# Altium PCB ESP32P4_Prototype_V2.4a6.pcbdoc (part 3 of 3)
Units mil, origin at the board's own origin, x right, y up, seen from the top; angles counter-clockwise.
Board outline 8474.8 x 7265.9 mil, 6 copper layers (Top Layer, GND, VCC, VCC1, GND1, Bottom Layer), stack 62.3 mil thick; 189 components, 155 nets, 775 pads, 406 vias.
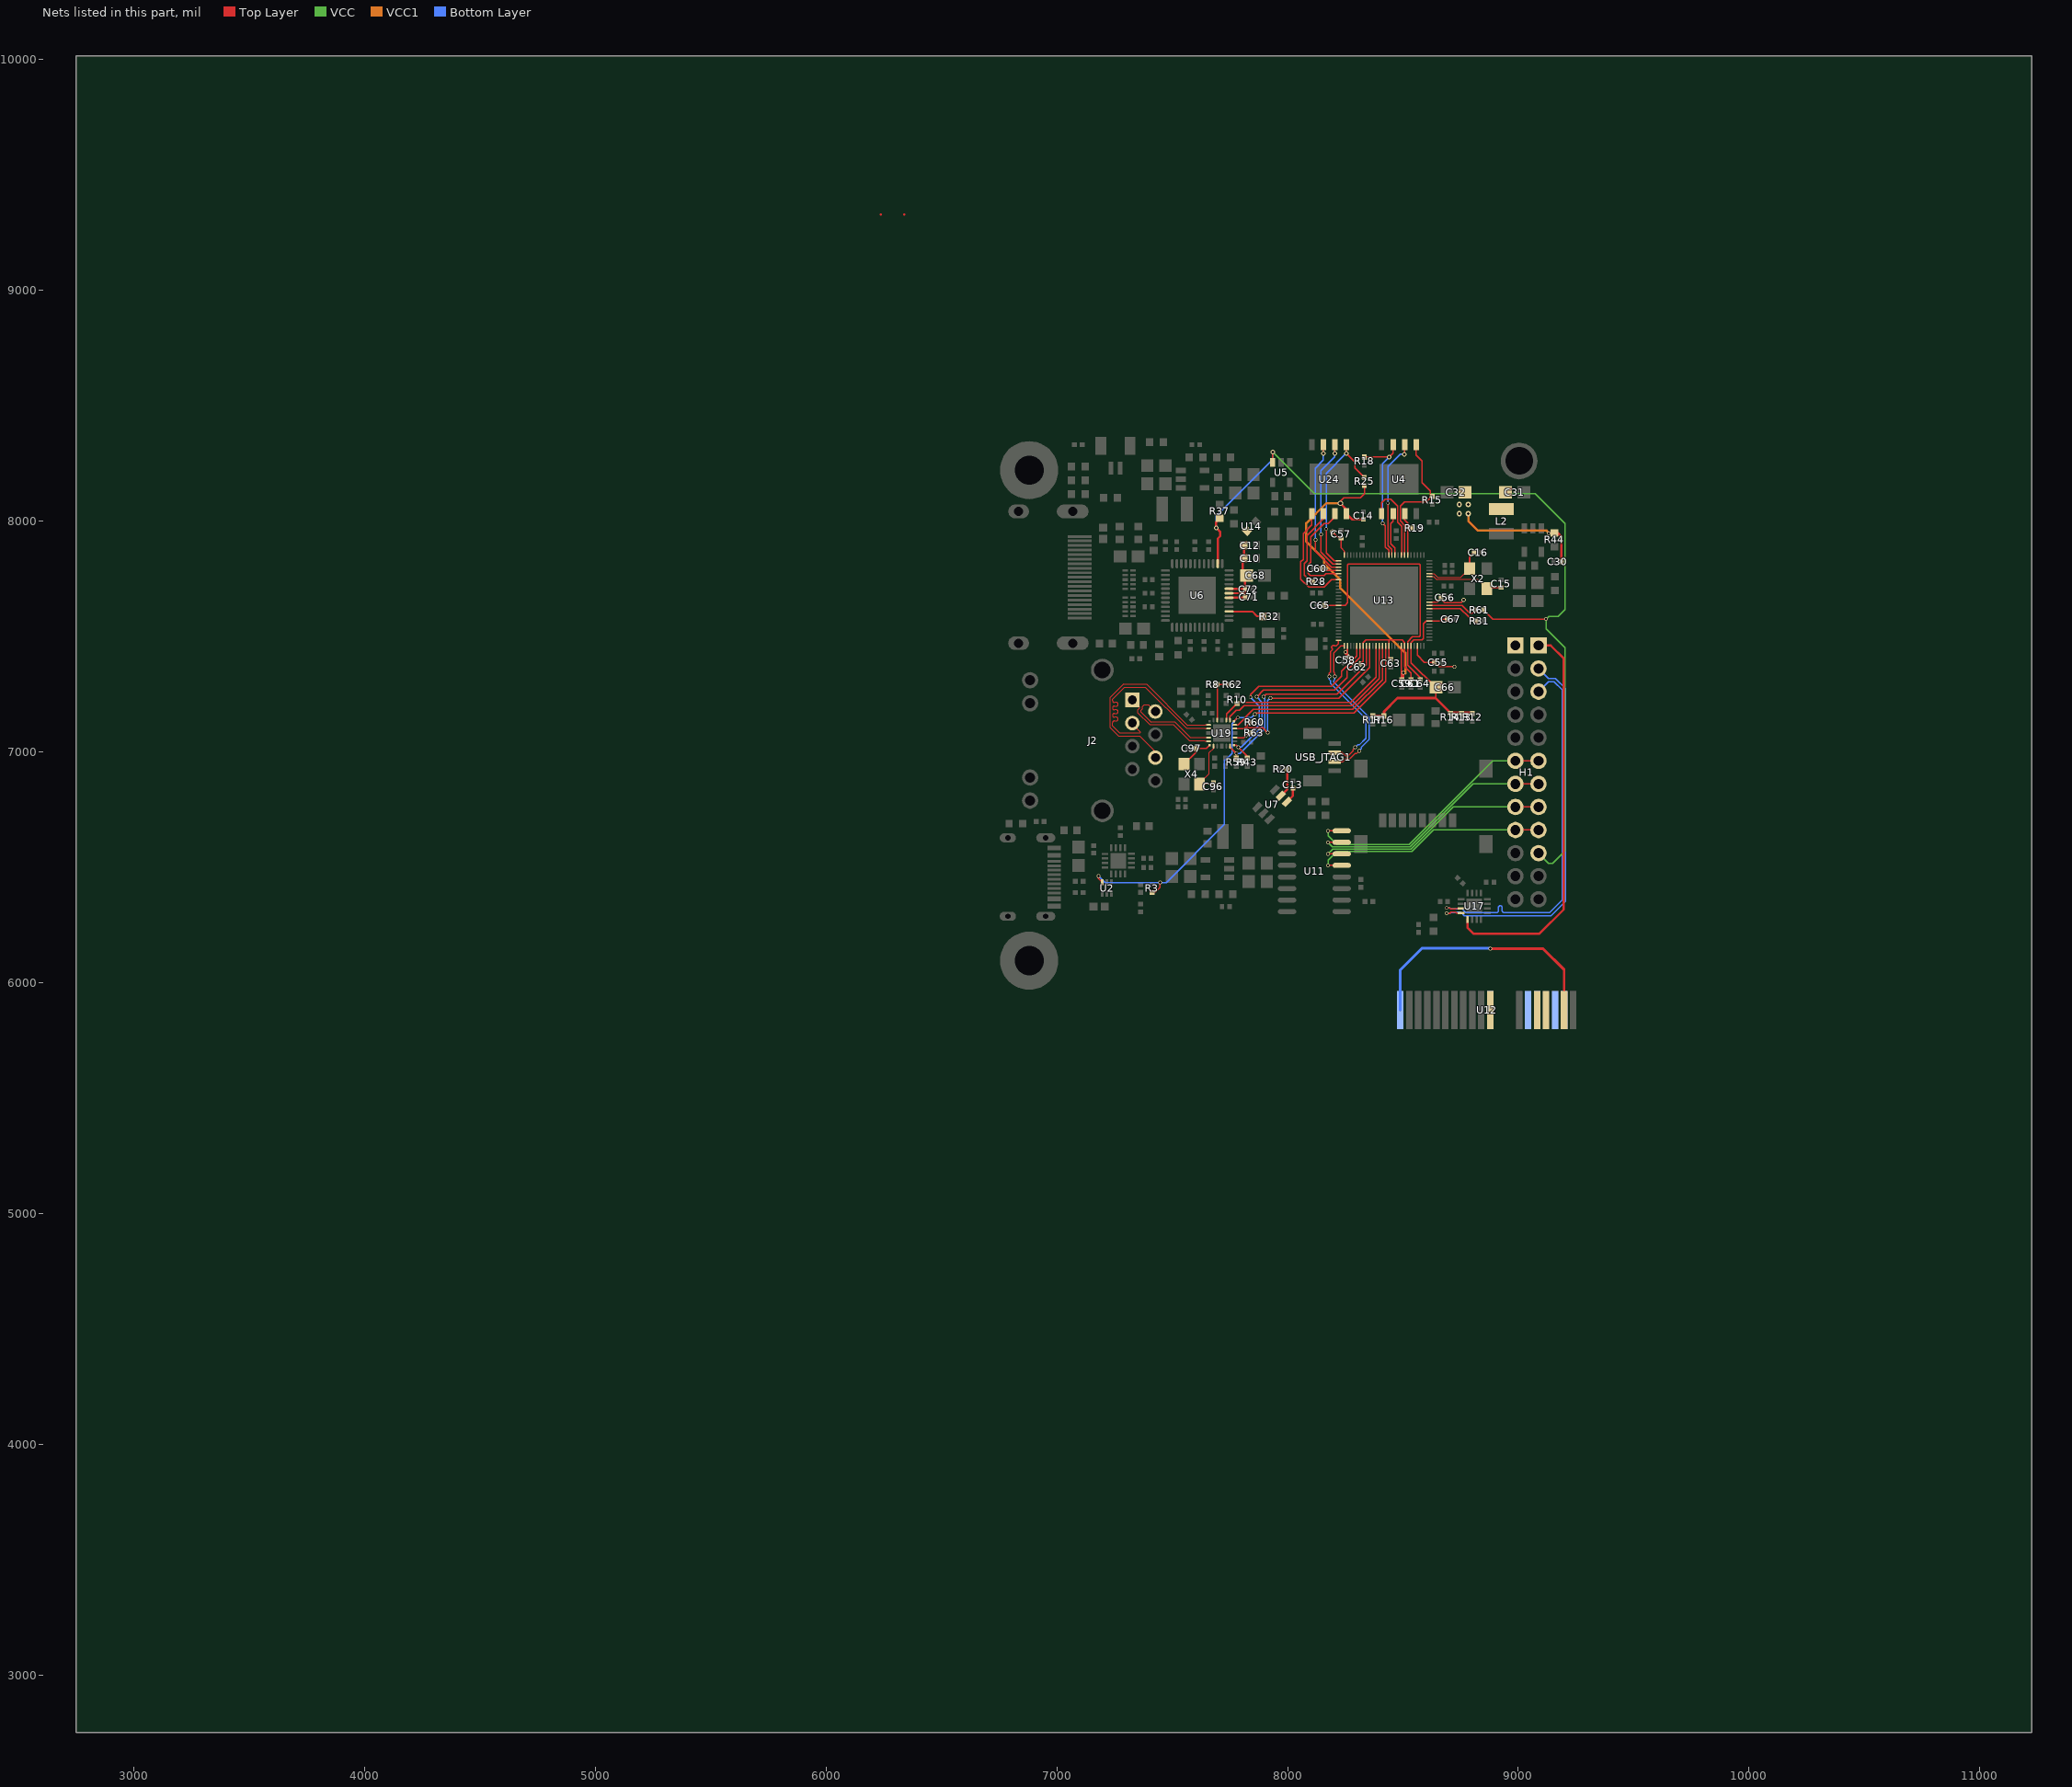
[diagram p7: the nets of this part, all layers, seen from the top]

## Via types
v1: diameter 15.7, hole 11.8, Top Layer to Bottom Layer, 168 vias
v2: diameter 23.6, hole 11.8, Top Layer to Bottom Layer, 139 vias
v3: diameter 19.7, hole 11.8, Top Layer to Bottom Layer, 91 vias
v4: diameter 23.6, hole 15.7, Top Layer to Bottom Layer, 8 vias

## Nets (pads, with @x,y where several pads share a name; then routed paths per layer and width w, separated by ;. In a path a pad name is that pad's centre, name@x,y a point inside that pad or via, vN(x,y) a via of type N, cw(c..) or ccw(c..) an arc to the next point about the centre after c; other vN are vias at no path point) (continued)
MS_SDA: H1.5 R37.1 R61.1 U5.3 U6.14 | length 4034.6
  Top Layer w5.9: R61.1@8849.6,7615 8889.1,7575.6 v1(9120.2,7575.6)
  Top Layer w6.1: U5.3@7935.2,8260.6 v3(7935.2,8299.9)
  Top Layer w10: U6.14@7697,7815.7 7697,7924 7708.8,7935.8 7708.8,7953 v3(7690.2,7971.6) 7690.2,7996.3 R37.1@7706.8,8012.9
  VCC w5.9: v3(7935.2,8299.9) 8116.5,8118.6 9073.2,8118.6 9202.9,7988.9 9202.9,7617.7 9172.6,7587.4 9132,7587.4 v1(9120.2,7575.6) 9120.2,7534.2 9202.9,7451.5 9202.9,6571.6 9148.7,6517.5 9131.5,6517.5 H1.5@9087.6,6561.4
  Bottom Layer w6.1: v3(7690.2,7971.6) 7690.2,8021.3 7935.2,8266.3 v3(7935.2,8299.9)
NET6: R20.1 U7.5 | length 130
  Top Layer w10: U7.5@7970.8,6810 7998.2,6837.4 7998.2,6919.4 R20.1@7991.6,6925.9
NET7: C13.2 U7.4 | length 69.4
  Top Layer w10: U7.4@7997.2,6783.5 8023.7,6810 C13.2@8023.7,6841.9
P4_FLASH_CK: R28.1 U24.6 | length 354.2
  Top Layer w5.9: R28.1@8108,7738.7 8100.8,7738.7 8073,7766.5 8073,7817.1 8083.8,7827.9 8083.8,7938.7 8154.9,8009.8 U24.6@8154.9,8040.3
P4_FLASH_CS: R25.2 U13.27 U24.1 | length 717.3
  Top Layer w5.9: v1(8168.1,7965.7) 8168.1,7862.3 8202,7828.4 U13.27@8220.9,7828.4 ; U24.1@8254.9,8339.5 v3(8254.9,8294.3) 8292,8257.2 8292,8230.1 R25.2@8332.8,8189.2
  Bottom Layer w5.9: v1(8168.1,7965.7) 8168.1,8207.5 v3(8254.9,8294.3)
P4_FLASH_D: U13.33 U24.5 | length 502.6
  Top Layer w5.9: U24.5@8104.9,8040.3 8104.9,7983.4 8067.8,7946.3 8067.8,7834.1 8057.2,7823.6 8057.2,7749.1 8092.7,7713.7 8157.6,7713.7 8189.7,7745.8 U13.33@8220.9,7745.8
P4_FLASH_HOLD: U13.31 U24.7 | length 457
  Top Layer w5.9: U24.7@8204.9,8032.3 8204.9,8018.5 8175.3,7988.9 8157.6,7988.9 8099.8,7931.1 8099.8,7821.6 8088.7,7810.5 8088.7,7774.4 8099.4,7763.7 8157.6,7763.7 8167.2,7773.3 U13.31@8220.9,7773.3
P4_FLASH_Q: U13.28 U24.2 | length 595.9
  Top Layer w5.9: v1(8144.5,7942.1) 8144.5,7866.4 8196.3,7814.7 U13.28@8220.9,7814.7 ; v3(8204.9,8294.2) U24.2@8204.9,8339.5
  Bottom Layer w5.9: v1(8144.5,7942.1) 8144.5,8217.9 8204.9,8278.3 v3(8204.9,8294.2)
P4_FLASH_WP: U13.29 U24.3 | length 611.9
  Top Layer w5.9: v1(8120.9,7918.5) 8120.9,7870.6 8190.6,7800.9 U13.29@8220.9,7800.9 ; v3(8154.9,8294.2) U24.3@8154.9,8339.5
  Bottom Layer w5.9: v1(8120.9,7918.5) 8120.9,8229.8 8154.9,8263.8 v3(8154.9,8294.2)
P4_VDDO1_FLASH: C14.1 C59.2 C60.2 R25.1 U13.30 U13.71 U24.8 | length 1612.7
  Top Layer w5: U13.71@8493.5,7459.4 8493.5,7352.8 ; 8493.5,7352.8 8493.5,7314.5 C59.2@8495.5,7312.6 C59.2@8498.5,7315.6 ; 8493.5,7352.8 v1(8502.6,7343.7) ; C59.2@8498.5,7315.6 8502.6,7319.7 v1(8502.6,7343.7) ; C59.2@8498.5,7315.6 8498.5,7339.6 v1(8502.6,7343.7)
  Top Layer w5.9: v4(8228.5,8077.5) 8228.5,8085.1 8244.8,8101.4 8315.6,8101.4 8333.3,8119.1 8333.3,8154.7 R25.1@8332.8,8155.2
  Top Layer w6.1: v3(8163.5,7794.1) 8170.5,7787.1 U13.30@8220.9,7787.1
  Top Layer w10: v4(8228.5,8077.5) 8254.9,8051.1 U24.8@8254.9,8032.3 8279.3,8007.8 C14.1@8323,8007.8
  Top Layer w11.8: C60.2@8144.6,7794.1 v3(8163.5,7794.1)
  VCC1 w10: v4(8228.5,8077.5) 8167.5,8077.5 8080.9,7990.9 8080.9,7911.3 8157.6,7834.6 8157.6,7816.9 8227.1,7747.4 8227.1,7712 8510.3,7428.8 8510.3,7340.3
P4_VDDO2_PSRAM: C61.2 C62.2 C63.2 U13.59 U13.67 U13.72 | length 549.6
  Top Layer w5: U13.59@8328.2,7459.4 8328.2,7474.3 8339.1,7485.2 8438.4,7485.2 ; C63.2@8447.6,7400.2 8438.4,7409.4 U13.67@8438.4,7459.4 8438.4,7485.2 ; U13.72@8507.3,7459.4 8507.3,7474 8496.1,7485.2 8438.4,7485.2
  Top Layer w5.9: C62.2@8314.3,7380.4 8328.2,7394.3 U13.59@8328.2,7459.4 ; U13.72@8507.3,7459.4 8507.3,7369 8534.9,7341.4 C61.2@8534.9,7312.6
P4_VDDO3_MIPI: C64.2 C65.2 U13.41 U13.73 | length 1146
  Top Layer w5: U13.41@8220.9,7635.5 8249.4,7635.5 8260.3,7646.4 8260.3,7809.5 8264.5,7813.6 8571,7813.6 8575.2,7809.5 8575.2,7502.9 8571,7498.8 8541.5,7498.8 8521.1,7478.4 U13.73@8521.1,7459.4
  Top Layer w5.9: U13.73@8521.1,7459.4 8521.1,7375.2 8574.2,7322 C64.2@8574.2,7312.6
  Top Layer w6.1: C65.2@8158.7,7635.5 U13.41@8220.9,7635.5
P4_VDDO4_SDIO: C66.2 C67.2 R12.1 R13.1 R14.1 R16.1 R17.1 U13.74 U13.85 | length 1019
  Top Layer w5: U13.74@8534.9,7459.4 8534.9,7474 8546.1,7485.2 8582.8,7485.2 8588.8,7491.1 8588.8,7555.4 8600,7566.6 U13.85@8614.6,7566.6
  Top Layer w5.9: U13.74@8534.9,7459.4 8534.9,7386.4 8641.9,7279.4 8641.9,7233 ; 8667.6,7573.7 8668.7,7574.8 C67.2@8690.8,7574.8
  Top Layer w6.1: U13.85@8614.6,7566.6 8660.5,7566.6 8667.6,7573.7
  Top Layer w11.8: R17.1@8370.2,7155.6 R16.1@8417.5,7155.6 8417.5,7174 8476.5,7233 8641.9,7233 8705.6,7169.4 R12.1@8799.4,7169.4
P4_XTAL_N: C15.1 U13.99 X2.3 | length 334.4
  Top Layer w4.1: U13.99@8614.6,7759.6 8632.8,7759.6 8646.4,7745.9 8825.5,7745.9 X2.3@8863.8,7707.6
  Top Layer w7.9: X2.3@8863.8,7707.6 8868.7,7712.6 C15.1@8925.3,7712.6
P4_XTAL_P: C16.2 U13.100 X2.1 | length 276.2
  Top Layer w4.1: U13.100@8614.6,7773.3 8634,7773.3 8651.4,7755.9 8750.7,7755.9 X2.1@8789,7794.3
  Top Layer w7.9: X2.1@8789,7794.3 8789,7845.5 C16.2@8808.4,7864.9
PERN0: U12.A17
PERP0: U12.A16
PERST#: U12.A11
PETN0: U12.B15
PETP0: U12.B14
PHY_LED0: R8.1 R62.1 U19.4 | length 206.7
  Top Layer w5.9: U19.4@7695,7138 7695,7290.7 R8.1@7692.8,7292.9 R62.1@7743.7,7292.9
PRSNT1#: U12.A1 U12.B17 | length 1136.5
  Top Layer w11.8: v1@8879.4,6148.7 8881.8,6146.4 9108.4,6146.4 9198.6,6056.2 U12.B17@9198.6,5880.8
  Bottom Layer w11.8: U12.A1@8488.6,5880.8 8488.6,6054.7 8582.6,6148.7 v1@8879.4,6148.7
  other v1: 8878.1,6146.4
PWR_SW1: H1.7 H1.8 U11.13 | length 1072.3
  Top Layer w5: v1(8175.8,6508) U11.13@8234.8,6508 U11.13@8259.4,6508 ; H1.8@8987.6,6661.4 H1.7@9087.6,6661.4
  VCC w5: v1(8175.8,6508) 8175.8,6530.7 8213.1,6568 8539,6568 8632.3,6661.4 H1.8@8987.6,6661.4
PWR_SW2: H1.9 H1.10 U11.14 | length 1055.1
  Top Layer w5: v1(8175.8,6558) U11.14@8234.8,6558 ; H1.10@8987.6,6761.4 H1.9@9087.6,6761.4
  VCC w5: v1(8175.8,6558) 8195.8,6578 8534.9,6578 8718.2,6761.4 H1.10@8987.6,6761.4
RD+: J2.3 U19.8 | length 927.1
  Top Layer w4.7: J2.3@7327.1,7125.2 7327.1,7122.4 7361.8,7087.7 7361.8,7083.6 7358.9,7080.7 7272.4,7080.7 7241,7112.2 7241,7126.4 cw(c7249,7126.4) 7249,7134.4 7257.7,7134.4 ccw(c7257.7,7142.4) 7257.7,7150.4 7249,7150.4 cw(c7249,7158.4) 7249,7166.4 7257.7,7166.4 ccw(c7257.7,7174.4) 7257.7,7182.4 7249,7182.4 cw(c7249,7190.4) 7249,7198.4 7257.7,7198.4 ccw(c7257.7,7206.4) 7257.7,7214.4 7249,7214.4 cw(c7249,7222.4) 7241,7222.4 7241,7227.8 7293.9,7280.7 7383.6,7280.7 7561.6,7102.7 7641.6,7102.7 7643.1,7101.1 U19.8@7658.1,7101.1
RD-: J2.6 U19.7 | length 922.7
  Top Layer w4.7: 7229,7107 7228.6,7107.3 7228.6,7233.4 7288.6,7293.4 7388.9,7293.4 7566.9,7115.4 7641.6,7115.4 7643.1,7116.9 U19.7@7658.1,7116.9 ; 7229.1,7107 7267.4,7068.6 7358.9,7068.6 7427.1,7000.4 J2.6@7427.1,6975.2
REFCLK+: U12.A13
REFCLK-: U12.A14
REXT_MS: R32.2 U6.3 | length 154.4
  Top Layer w7.9: U6.3@7746.2,7609 7846.6,7609 7868.3,7587.4 R32.2@7891.7,7587.4
RMII_CLK: R10.1 U13.63 U19.2 | length 876.2
  Top Layer w5.9: U19.2@7734.4,7138 7735.7,7139.3 7735.7,7165 7780.8,7210.1 R10.1@7781.6,7210.1 7786.5,7215 8273.9,7215 8383.3,7324.4 U13.63@8383.3,7459.4
RMII_CRS_DV: R63.1 U13.57 U19.20 | length 889.1
  Top Layer w5.9: U19.20@7771.3,7061.8 7809.9,7061.8 v1(7818.9,7070.7) 7831.1,7082.9 R63.1@7838.7,7082.9 ; v1(7839.3,7236.9) 7839.3,7247.4 7875.6,7283.7 8190.6,7283.7 8234.4,7327.5 8234.4,7350.5 8300.6,7416.7 U13.57@8300.6,7459.4
  Bottom Layer w5.9: v1(7818.9,7070.7) 7832.7,7070.7 7878.1,7116 7878.1,7198.1 v1(7839.3,7236.9)
RMII_RX_ER_GPIO31: R60.1 U13.61 U19.22 | length 919.1
  Top Layer w5.9: U19.22@7771.3,7101.1 7812.1,7101.1 7815.9,7105 ; R60.1@7839.7,7128.7 7815.9,7105 ; v1(7913.9,7083.7) 7892.6,7105 7815.9,7105 ; v1(7925.3,7233) 8221.9,7233 8355.7,7366.8 U13.61@8355.7,7459.4
  Bottom Layer w5.9: v1(7913.9,7083.7) 7913.9,7221.5 v1(7925.3,7233)
RMII_RXD0: R43.1 U13.58 U19.18 | length 953.7
  Top Layer w5.9: U19.18@7766.9,7029.3 7777.3,7029.3 v1(7786.2,7020.4) 7825,6981.6 R43.1@7825,6972.5 ; v1(7866.3,7238.9) 7896.1,7268.7 8205.1,7268.7 8258,7321.6 8258,7354.1 8314.4,7410.5 U13.58@8314.4,7459.4
  Bottom Layer w5.9: v1(7786.2,7020.4) 7800.5,7020.4 7889.9,7109.8 7889.9,7215.3 v1(7866.3,7238.9)
RMII_RXD1: R59.1 U13.60 U19.17 | length 957.4
  Top Layer w5.9: U19.17@7750.1,7024.9 7750.1,7021.3 v1(7777.7,6993.7) R59.1@7777.7,6972.5 ; v1(7895.8,7238.9) 7907.6,7250.7 8214.6,7250.7 8342,7378.1 U13.60@8342,7459.4
  Bottom Layer w5.9: v1(7777.7,6993.7) 7793.8,6993.7 7901.7,7101.6 7901.7,7233 v1(7895.8,7238.9)
RMII_TX_EN: U13.64 U19.1 | length 871
  Top Layer w5.9: U19.1@7750.1,7138 7750.1,7152 7778.1,7180 7790.7,7180 7810.7,7200 8278.9,7200 8397.1,7318.2 U13.64@8397.1,7459.4
RMII_TXD0: U13.65 U19.23 | length 867.8
  Top Layer w5.9: U19.23@7771.3,7116.9 7785.1,7116.9 7851.9,7183.7 8282.6,7183.7 8410.9,7312 U13.65@8410.9,7459.4
RMII_TXD1_GPIO35: R3.2 U2.6 U13.66 U19.24 | length 2130.3
  Top Layer w5.9: U19.24@7766.9,7133.6 v1@7782.1,7148.9 ; v1(7858.9,7163.7) 7863.9,7168.7 8287.6,7168.7 8424.6,7305.7 U13.66@8424.6,7459.4
  Top Layer w6.1: v1(7180.3,6462.4) 7180.3,6451.5 U2.6@7197,6434.8 ; R3.2@7412.6,6391.7 7425.6,6391.7 7447.6,6413.7 v1(7447.6,6433.7)
  Bottom Layer w5.9: v1(7180.3,6462.4) 7209,6433.7 v1(7447.6,6433.7) 7473.9,6433.7 7726.5,6686.3 7726.5,6961.4 7758.9,6993.7 7758.9,7123.7 v1(7783.9,7148.7) ; v1@7782.1,7148.9 7844.1,7148.9 v1(7858.9,7163.7)
RST_SW1: H1.11 H1.12 U11.15 | length 1095.9
  Top Layer w5: v1(8175.8,6608) U11.15@8234.8,6608 ; H1.12@8987.6,6858.7 H1.12@8987.6,6861.4 H1.11@9087.6,6861.4
  VCC w5: v1(8175.8,6608) 8175.8,6606.6 8194.4,6588 8530.7,6588 8804.1,6861.4 H1.12@8987.6,6861.4
RST_SW2: H1.13 H1.14 U11.16 | length 1189.5
  Top Layer w5: v1(8175.8,6658) U11.16@8234.8,6658 U11.16@8259.4,6658 ; H1.14@8984.4,6961.4 H1.14@8987.6,6961.4 ; H1.14@8987.6,6958.7 H1.14@8987.6,6961.4 ; H1.13@9087.6,6961.4 H1.14@8987.6,6961.4
  VCC w5: v1(8175.8,6658) 8175.8,6636.1 8213.9,6598 8526.6,6598 8889.9,6961.4 H1.14@8987.6,6961.4
SCL: R31.2 U13.89 | length 223.4
  Top Layer w5.9: U13.89@8614.6,7621.8 8748,7621.8 8785.6,7584.2 8798.8,7584.2 R31.2@8815.5,7567.5
SDA: R61.2 U13.90 | length 223.2
  Top Layer w5.9: U13.90@8614.6,7635.5 8755.7,7635.5 8792.9,7598.3 8798.8,7598.3 R61.2@8815.5,7615
SPI1_CLK_GPIO9: U4.6 U13.10 | length 191.3
  Top Layer w5.9: U4.6@8457.4,8032.2 8457.4,7999.4 8447,7988.9 8447,7902.9 8466,7884 U13.10@8466,7853.1
SPI1_CS_GPIO7: R15.2 U4.1 U13.7 | length 620.8
  Top Layer w5.9: U13.7@8507.3,7853.1 8507.3,7981.8 8488.3,8000.7 8488.3,8065.7 8506.1,8083.4 8600.5,8083.4 8618.3,8101.1 8618.3,8130.7 8582.8,8166.1 8582.8,8260.6 8557.4,8286 U4.1@8557.4,8331.5
SPI1_IO0_GPIO8: U4.5 U13.8 | length 355.2
  Top Layer w5.9: U4.5@8407.4,8032.2 8407.4,8079.3 8423.4,8095.2 8447,8095.2 8476.5,8065.7 8476.5,7994.8 8494.2,7977.1 8494.2,7853.8 U13.8@8493.5,7853.1
SPI1_IO1_GPIO10: U4.2 U13.11 | length 525.6
  Top Layer w5.9: v1(8435.2,8077.5) 8435.2,7894.4 8452.2,7877.4 U13.11@8452.2,7853.1 ; v3(8506.1,8290.1) 8507.4,8291.5 U4.2@8507.4,8331.4
  Bottom Layer w5.9: v1(8435.2,8077.5) 8435.2,8237 8488.3,8290.1 v3(8506.1,8290.1)
SPI1_IO2_GPIO11: R18.2 U4.3 U13.12 | length 616.9
  Top Layer w5.9: R18.2@8332.8,8277.6 8333.5,8278.3 v3(8441.1,8278.3) 8457.4,8294.6 U4.3@8457.4,8331.4 ; v1(8411.7,7991.5) 8423.4,7979.9 8423.4,7888.5 8438.4,7873.5 U13.12@8438.4,7853.1
  Bottom Layer w5.9: v1(8411.7,7991.5) 8411.7,8248.9 v3(8441.1,8278.3)
SPI1_IO3_GPIO6: R19.1 U4.7 U13.6 | length 184.8
  Top Layer w5.9: U4.7@8507.4,8032.2 8507.4,8005.3 8521.1,7991.6 U13.6@8521.1,7853.1
TD+: J2.1 U19.11 | length 428.9
  Top Layer w4.7: J2.1@7327.1,7225.2 7358.3,7194 7358.3,7189.9 7351.8,7183.4 7351.8,7169.3 7404.6,7116.6 7506.6,7116.6 7575.6,7047.5 7641.6,7047.5 7643.1,7046 U19.11@7658.1,7046
TD-: J2.2 U19.10 | length 428.9
  Top Layer w4.7: J2.2@7420.4,7180.8 7397.7,7203.5 7378.1,7203.5 7371.7,7197.1 7371.7,7186.2 7363.9,7178.4 7363.9,7174.3 7409,7129.3 7511.8,7129.3 7580.8,7060.2 7641.6,7060.2 7643.1,7061.8 U19.10@7658.1,7061.8
USB1P1_N0: U13.52 USB_JTAG1.2 | length 696.1
  Top Layer w6.1: v1(8181,7327.5) 8181,7341.4 8185.8,7346.2 8185.8,7434.2 8192.5,7440.9 ; 8192.43,7449.13 cw(c8196.6,7453.3) 8192.43,7457.47 ; 8192.5,7457.5 8195.5,7460.5 ; 8192.57,7440.93 ccw(c8188.4,7445.1) 8192.57,7449.27 ; 8195.53,7460.57 cw(c8199.7,7456.4) 8203.87,7460.57 ; 8203.73,7460.43 ccw(c8207.9,7464.6) 8212.07,7460.43 ; USB_JTAG1.2@8203.9,6996.7 8237.6,6996.7 8250.2,6984 8263.9,6984 8283.7,7003.8 8283.7,7010.6 v1(8293.6,7020.4) ; 8212.1,7460.5 8220.9,7469.3 U13.52@8220.9,7484
  Bottom Layer w6.1: v1(8181,7327.5) 8181,7313.5 8185.8,7308.7 8185.8,7296.8 8339.2,7143.4 8339.2,7059.3 8310.2,7030.3 8303.4,7030.3 v1(8293.6,7020.4)
USB1P1_P0: U13.53 USB_JTAG1.3 | length 694.1
  Top Layer w6.1: USB_JTAG1.3@8203.9,6957.3 8237.6,6957.3 8250.2,6969.9 8269.7,6969.9 8293.6,6993.9 8300.4,6993.9 v1(8310.3,7003.7) ; v1(8204.7,7327.5) 8204.7,7341.4 8199.9,7346.2 8199.9,7428.4 8230.9,7459.4 U13.53@8245.5,7459.4
  Bottom Layer w6.1: v1(8204.7,7327.5) 8204.7,7313.5 8199.9,7308.7 8199.9,7302.6 8353.3,7149.2 8353.3,7053.5 8320.1,7020.3 8320.1,7013.6 v1(8310.3,7003.7)
USB2_D+: H1.19 U17.7 | length 1689.9
  Top Layer w5.9: v1(8689.2,6323.6) 8703,6323.6 8707.8,6318.7 8728.6,6318.7 8731.5,6321.6 U17.7@8752.1,6321.6
  Bottom Layer w6.1: v1(8689.2,6323.6) 8703.2,6323.6 8707.9,6318.8 8756.9,6318.8 8771.8,6303.9 8905.9,6303.9 ccw(c8905.9,6311.9) 8913.9,6311.9 8913.9,6325.4 cw(c8921.9,6325.4) 8929.9,6325.4 8929.9,6311.9 ccw(c8937.9,6311.9) 8937.9,6303.9 9136,6303.9 9191.1,6359 9191.1,7268.5 9155.2,7304.3 9130.5,7304.3 H1.19@9087.6,7261.4
USB2_D-: H1.21 U17.8 | length 1691.2
  Top Layer w5.9: v1(8689.2,6300) 8703,6300 8707.8,6304.8 8728.6,6304.8 8731.5,6301.9 U17.8@8752.1,6301.9
  Bottom Layer w6.1: v1(8689.2,6300) 8703.2,6300 8707.9,6304.7 8751,6304.7 8766,6289.8 9141.8,6289.8 9205.2,6353.2 9205.2,7274.3 9161.1,7318.4 9130.5,7318.4 H1.21@9087.6,7361.4
USB3V3_MS: C10.2 C12.2 C68.2 C71.2 C72.2 U6.6 U6.7 U6.8 U14.2 | length 428
  Top Layer w6.1: U6.7@7746.2,7687.8 7816.1,7687.8
  Top Layer w10: U6.6@7746.2,7668.1 7814.1,7668.1 C71.2@7816.1,7670 7816.1,7687.8 7816.1,7747.7 7805,7758.7 C10.2@7805,7823.7 ; U6.8@7746.2,7707.5 7813.6,7707.5 C72.2@7815.5,7705.5 ; C10.2@7811.2,7823.6 C12.2@7811.2,7882.6
USB_VBUS: H1.23 U17.9 | length 1727.9
  Top Layer w9.8: U17.9@8779.7,6274.4 8779.7,6238.9 8807.2,6211.4 9090.7,6211.4 9197,6317.7 9197,7404.3 9139.9,7461.4 H1.23@9087.6,7461.4
USB_VBUS0: H1.24
VCC_HP: C30.2 C31.2 C32.2 C55.2 C56.2 C57.2 C58.2 L2.2 R44.2 U13.26 U13.54 U13.76 U13.91 | length 1217.5
  Top Layer w5: U13.76@8562.4,7459.4 8562.4,7418.9 8592.5,7388.7 C55.2@8636.1,7388.7 8655.8,7369 v1@8721.6,7369
  Top Layer w6.1: v2(8195.2,7953.7) 8221.7,7927.2 C57.2@8232.6,7927.2 8232.6,7883.7 8245.5,7870.8 U13.26@8245.5,7853.1 ; v1@8257,7431.8 8259.3,7434.1 ; U13.54@8259.3,7459.3 8259.3,7444.6 ; C58.2@8263.8,7410.1 C58.2@8259.3,7414.6 ; U13.91@8614.6,7649.3 8648.2,7649.3 8660.2,7661.3 C56.2@8666.1,7661.3 ; C56.2@8666.1,7668.7 C56.2@8666.1,7661.3 ; v3(8764,7658.9) 8752.2,7647.1 8680.2,7647.1 C56.2@8666.1,7661.3 ; R44.2@9155.8,7947.6 R44.2@9157,7948.7 ; v1(8250.4,7431.8) 8250.4,7435.7 8259.3,7444.6 ; v1(8250.4,7431.8) 8259.3,7422.9 ; v1(8250.4,7431.8) 8250.4,7423.5 C58.2@8259.3,7414.6 ; C58.2@8259.3,7414.6 8259.3,7422.9 ; 8259.3,7422.9 8259.3,7434.1 ; 8259.3,7434.1 8259.3,7444.6
  Top Layer w10: v1(9132,7947.6) 9155.8,7947.6 R44.2@9173.4,7947.6 ; R44.2@9157,7948.7 9172.2,7948.7 R44.2@9173.4,7947.6 ; C30.2@9187.6,7824.1 9187.6,7933.3 R44.2@9173.4,7947.6
  VCC1 w10: v2(8783.6,8032.2) 8783.6,8000.7 8825,7959.4 9122.7,7959.4 v1@9133.7,7948.4
  other v1: 8722.6,7368.7
  other v2: 8744.2,8032.2 8744.2,8071.6 8783.6,8071.6
WAKE#: U12.B11
WP:  | length 0
XI: C96.1 U19.13 X4.3 | length 252.7
  Top Layer w4.7: X4.3@7617.3,6862.4 X4.3@7618.3,6862.4 ; X4.3@7618.3,6861 X4.3@7618.3,6862.4 ; C96.1@7678.9,6867.2 7674,6862.4 X4.3@7618.3,6862.4 ; U19.13@7679.3,7024.9 7679.3,7016.1 7658.9,6995.7 7658.9,6903.9 7618.3,6863.3 X4.3@7618.3,6862.4
XO: C97.2 U19.12 X4.1 | length 155
  Top Layer w5.9: X4.1@7551.3,6947.6 7601.3,6997.6 C97.2@7601.3,7014.5 7647.8,7014.5 U19.12@7662.6,7029.3
pads on no net: H1.15 H1.16 HDMI1.13 HDMI1.14 J2.7 U1.10 U1.11 U1.14 U1.15 U1.16 U6.9 U6.10 U6.11 U6.12 U6.37 U6.38 U6.45 U12.A2 U12.A3 U12.A5 U12.A6 U12.A7 U12.A8 U12.A9 U12.A10 U12.B1 U12.B2 U12.B5 U12.B6 U12.B8 U12.B9 U12.B12 U13.13 U13.20 U13.35 U13.36 U13.37 U13.38 U13.39 U13.40 U13.42 U13.43 U13.44 U13.45 U13.46 U13.47 U13.95 U13.97 U13.98 U17.10 U17.11 U17.12 U17.13 U17.14 U17.15 U17.16 USB2.A8 USB2.B8

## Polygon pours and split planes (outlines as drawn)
USB3V3_MS on Top Layer (solid, remove dead copper, pour order 216): 7833.4,7808.4 7854.9,7786.8 7854.9,7731.6 7850.7,7727.4 7837.6,7727.4 7828.6,7718.5 7828.6,7658.9 7826.2,7656.5 7803.9,7656.5 7798.8,7661.7 7730.1,7661.7 7725.3,7666.5 7725.3,7709 7729.3,7713 7767.9,7713 7791.9,7736.9 7791.9,7961.1 7808.3,7977.5 7825.9,7977.5 7833.4,7970
P4_VDDO4_SDIO on Top Layer (solid, remove dead copper, pour order 232): 8575.2,7233 8605.2,7263 8605.2,7316.1 8667.4,7316.1 8677.3,7306.2 8677.3,7198 8676.9,7198 8641.9,7233
P4_VDDO1_FLASH on VCC1 (solid, remove dead copper): 8526.6,7332.5 8472.6,7332.5 8472.6,7359 8506.1,7392.5 8510.3,7392.5 8526.6,7376.2
GND on GND (solid, remove dead copper): 3444.5,9137 3444.5,3292 10914.5,3292 10914.5,9137
GND on GND1 (solid, remove dead copper): 3377,8845 3377,3000 10847,3000 10847,8845
GND on Bottom Layer (solid, remove dead copper, pour order 72): 4410.4,9277.5 4410.4,4267.5 10745.4,4267.5 10745.4,9277.5
GND on Top Layer (solid, remove dead copper, pour order 236): 3000,8774.3 3000,4579.8 10974.8,4579.8 10974.8,8774.3
GND on VCC1 (solid, remove dead copper): 3195.1,9241.3 3195.1,3396.3 10665.1,3396.3 10665.1,9241.3
GND on VCC (solid, remove dead copper): 3132.6,9765.9 3132.6,5175.9 10817.6,5175.9 10817.6,9765.9
3V3_SYS on VCC (solid, remove dead copper): 8086.8,7853.9 8108.7,7832 8220.9,7832 8304.5,7915.6 8594.5,7915.6 8669.5,7840.6 8669.5,7717.4 8659.6,7707.5 8451.4,7707.5 8143,7399.1 8143,7324.1 8228.3,7238.8 8292.8,7238.8 8340.2,7286.3 8340.2,7351.3 8355.7,7366.8 8372.6,7366.8 8386.4,7353.1 8386.4,7264 8470.6,7179.8 8617.7,7179.8 8663.8,7225.8 8663.8,7273 8546.7,7390.1 8546.7,7422 8566.4,7441.7 8595.7,7441.7 8608.7,7428.7 8608.7,7409.8 8684.1,7334.4 8725.1,7334.4 8764,7373.3 8764,7567.7 8854.5,7658.2 8953.5,7658.2 8964.6,7647.1 8964.6,7594 8946.9,7576.3 8899.7,7576.3 8828.9,7505.5 8828.9,7446.5 8865.2,7410.2 8865.2,7193.4 8738.1,7066.3 8265.1,7066.3 8160.8,6962 8160.8,6727.3 8086.9,6653.5 8086.9,6571.8 8215.3,6443.4 8840.7,6443.4 8852.5,6431.6 8852.5,6414.1 8776.7,6338.3 8042.1,6338.3 7826.8,6553.7 7762.6,6553.7 7692.6,6623.7 7510.4,6623.7 7372.6,6485.9 7280.8,6485.9 7227.8,6538.8 7227.8,6598.9 7372.6,6743.7 7891.8,6743.7 8058.1,6910 8058.1,7641.4 7946.3,7753.2 7946.3,7832 8047,7932.8 8047,7997.9 7941.1,8103.8 7941.1,8144.3 7957,8160.2 7968.7,8160.2 7980.5,8148.4 7980.5,8116.7 8086.8,8010.4
3V3_SYS on VCC (solid, remove dead copper): 8352.5,8101.7 8387.4,8101.7 8429.7,8059.4 8476.9,8059.4 8541,7995.3 8611.9,7995.3 8621.8,7985.4 8621.8,7975.6 8607.3,7961.2 8543.2,7961.2 8528.7,7946.6 8529.3,7945.9 8529.3,7928.8 8545.8,7912.3 8545.8,7899.2 8548.6,7896.4 8523.1,7896.4 8479.8,7853.1 8444.9,7853.1 8407.5,7890.4 8482.4,7965.3 8482.4,7983 8460.4,8005 8413.2,8005 8340.7,8077.5 8340.7,8089.9
3V3_SYS on Top Layer (solid, remove dead copper, pour order 234): 8539.6,7174.1 8590.2,7174.1 8619.9,7144.4 8654.1,7144.4 8666.2,7132.3 8666.2,7099.2 8584.9,7017.9 8579.5,7017.9 8576.9,7020.4 8576.9,7067.7 8529.7,7114.9 8529.7,7164.2
VCC_HP on Top Layer (solid, remove dead copper, pour order 190): 8724.6,8030.3 8724.6,8107 8771.8,8154.3 8915.1,8154.3 8989,8080.3 8989,8020.5 8799.2,8020.5 8791.3,8012.6 8742.3,8012.6
VCC_HP on VCC1 (solid, remove dead copper): 8827.6,7813.7 8642.6,7998.7 8642.6,8033.7 8696.7,8087.8 8799.2,8087.8 8801.2,8087.8 8827.6,8061.4
3V3_MS on VCC (solid, remove dead copper): 7838.7,7424.5 7362.9,7424.5 7342.7,7404.3 7277.7,7404.3 7265.9,7416.1 7265.9,7491.1 7287.8,7491.1 7303.7,7475.2 7585,7475.2 7620.4,7510.6 7649.8,7510.6 7684,7476.3 7770.4,7476.3 7808.1,7514 7808.1,7533.7 7744.2,7597.6 7744.2,7759.1 7709.8,7793.5 7503.1,7793.5 7503.1,7860 7513.9,7870.8 7529.3,7870.8 7547,7853.1 7578.9,7853.1 7592.7,7839.3 7607.1,7839.3 7636.4,7868.7 7671.4,7868.7 7766.9,7964.3 7766.9,8040.3 7813.2,8086.6 7901.5,8086.6 7937.7,8050.4 7937.7,7740.6 8044.8,7633.6 8044.8,6912 7925.1,6792.4 7881.5,6835.9 7881.5,6880.2 7953.4,6952.1 7953.4,7309.8
VCC_HP on Top Layer (solid, remove dead copper, pour order 230): 8644.9,7649.3 8662.4,7666.8 8668.8,7666.8 8688.4,7647.1 8692.8,7647.1 8689.2,7643.6 8650.6,7643.6
3V3_MS on Top Layer (solid, remove dead copper, pour order 210): 7859.4,7958.7 7761.4,8056.7 7689.6,8056.7 7612.6,8133.7 7612.6,8153.7 7617.6,8158.7 7908.7,8158.7 7908.7,8084.5 7925.1,8068.1 7957.8,8068.1 7968.7,8057.2 7968.7,8027 7957.8,8016.1 7920.5,8016.1 7863.1,7958.7
3V3_SYS on Top Layer (solid, remove dead copper, pour order 228): 7921.5,8084.6 7917.6,8088.5 7917.6,8194.7 7945.9,8194.7 7984.2,8156.4 7984.2,8136.7 7972.9,8125.4 7972.9,8093.3 7964.3,8084.6
GPIO13 on Bottom Layer (solid, remove dead copper, pour order 70): 8066.1,7637.2 8066.1,7661.2 8075,7670 8098.9,7670 8102.8,7673.9
3V3_MS on Top Layer (solid, remove dead copper, pour order 226): 7921.4,6796 7881.5,6835.9 7953.9,6908.2 7968.7,6908.2 7974.6,6902.3 7974.6,6849.2
3V3_SYS on Top Layer (solid, remove dead copper, pour order 224): 7795.9,6705.9 7874.2,6784.2 7892,6766.4 7862.4,6736.7 7862.4,6693.9 7945.8,6610.5 7945.8,6494 7940.5,6488.7 7801.2,6488.7 7795.9,6494
3V3_SYS on Top Layer (solid, remove dead copper, pour order 220): 7710.8,6946.6 7719.7,6955.5 7741.2,6955.5 7750.1,6946.6 7750.1,6902.4 7767.9,6884.6 7792.5,6884.6 7805.3,6897.4 7805.3,6946.6 7814.2,6955.5 7835.7,6955.5 7844.6,6946.6 7844.6,6918.3 7832.8,6906.5 7832.8,6878.7 7803.3,6849.2 7750.1,6849.2 7710.8,6888.5
3V3_MS on Top Layer (solid, remove dead copper, pour order 198): 7268.8,7483.9 7277.8,7492.9 7325,7492.9 7336.8,7481.1 7336.8,7392.5 7330.9,7386.6 7295.6,7386.6 7268.8,7413.4
5V_SYS on VCC1 (solid, remove dead copper): 7519.8,6613 7519.8,6583 7653.1,6583 7653.1,6613
P4_VDDO1_FLASH on VCC1 (solid, remove dead copper): 8152.6,7832.4 8153.9,7833.7 8153.9,7845.2 8195.7,7803.4 8195.7,7776.5 8194.7,7775.4 8164.1,7775.4 8152.6,7786.9
VCC_HP on VCC1 (solid, remove dead copper): 8182.1,7940.8 8182.1,7985.6 8256,8059.5 8671.8,8059.5 8827.6,7903.7 8827.6,7382 8708.3,7262.6 8372.9,7262.6 8239.1,7396.4 8239.1,7434.8 8244.6,7440.3 8262.6,7440.3 8376.7,7326.2 8695,7326.2 8707.6,7338.7 8707.6,7388.7 8753.7,7434.8 8753.7,7607.8 8747.3,7614.1 8747.3,7655.3 8753.7,7661.6 8753.7,7876.9 8626,8004.6 8242.4,8004.6 8208.6,7970.9 8208.6,7940.8
A3V3_MS on Top Layer (solid, remove dead copper, pour order 146): 7455.8,7541.4 7467.6,7529.6 7467.6,7502.8 7403.5,7438.7 7357.6,7438.7 7352.6,7443.7 7352.6,7525 7369,7541.4
5V_SYS on Top Layer (solid, remove dead copper, pour order 144): 7175,6311.2 7084.1,6311.2 7044.2,6351.1 6960.9,6351.1 6960.9,6374.8 7146.5,6374.8 7176,6345.2 7176,6312.2
5V_SYS on Top Layer (solid, remove dead copper, pour order 196): 7188.1,6523.4 7145,6480.2 7074.6,6480.2 7014.7,6540.1 6960.9,6540.1 6960.9,6563.7 7032.1,6563.7 7053.2,6542.7 7121.8,6542.7 7142.9,6563.7 7187.2,6563.7 7188.1,6562.8
3V3_SYS on Top Layer (solid, remove dead copper, pour order 206): 8545.6,8056 8547.1,8057.6 8588.6,8057.6 8617.1,8086.1 8637.9,8086.1 8638.7,8085.4 8638.7,8062.1 8630.9,8054.3 8630.9,8019.9 8624.3,8013.4 8624.3,7984.4 8599.2,7959.2 8557.3,7959.2 8557,7959.5 8557,7980.7 8545.6,7992.1
3V3_SYS on Top Layer (solid, remove dead copper, pour order 200): 7912,7839.3 7959.8,7794.1 8007.2,7794.1 8021.8,7811.6 8050.2,7840 8050.2,7894.4 7912,7894.4
A1V2_MS on VCC (solid, remove dead copper): 7446.2,7766.5 7446.2,7727.1 7414.3,7695.2 7414.3,7680.3 7446.2,7648.4 7446.2,7609 7442.7,7605.5 7406,7605.5 7382.8,7628.7 7382.8,7858.9 7392.6,7868.7 7434.9,7868.7 7446.2,7857.4
5V_SYS on VCC (solid, remove dead copper): 7060,6321.6 7060,6551.9 7072.6,6564.6 7184.4,6564.6 7277.9,6471.1 7380,6471.1 7522.6,6613.7 7603.4,6613.7 7612.8,6604.3 7612.8,6556.6 7369,6312.8 7068.8,6312.8
$4N12791 on VCC (solid, remove dead copper): 7166.3,6693.8 7142.6,6717.4 7142.6,7380 7166.3,7403.6 7224.2,7403.6 7247.9,7380 7247.9,6717.4 7224.2,6693.8
$5N70958 on VCC (solid, remove dead copper): 6808.2,7418.7 6725.2,7501.7 6725.2,8025.7 6783.2,8083.7 7114.5,8083.7 7138.9,8059.3 7138.9,7433.1 7124.5,7418.7
A3V3_MS on VCC1 (solid, remove dead copper): 7424.2,7692.4 7455.6,7723.8 7455.6,7887.3 7468.7,7900.3 7492.3,7900.3 7504.4,7888.2 7504.4,7543.1 7566.9,7480.6 7659.5,7480.6 7692.6,7513.7 7707.6,7513.7 7712.6,7508.7 7712.6,7483.7 7652.6,7423.7 7527.6,7423.7 7466.4,7484.9 7418.2,7484.9 7407.6,7495.5 7407.6,7518.7 7457.6,7568.7 7457.6,7649.7 7424.2,7683.2
1V2_SYS on VCC1 (solid, remove dead copper): 7512.4,7793.5 7582.6,7863.7 7582.6,7888.7 7562.6,7908.7 7416.6,7908.7 7351.3,7973.9 7351.3,8102.2 7360.1,8111 7443.1,8111 7641.9,7912.2 7641.9,7828 7607.6,7793.7 7572.6,7793.7 7552.6,7773.7 7552.6,7586.1 7598.6,7540.1 7598.6,7494.7 7592.6,7488.7 7567.6,7488.7 7512.4,7543.9
3V3_SYS on Top Layer (solid, remove dead copper, pour order 180): 9040,7889.1 9040,7599.1 8901.8,7599.1 8895.8,7605.1 8895.8,7652.3 8901.7,7658.2 8946.7,7658.2 8970,7681.6 8970,7849.1 9015,7894.1 9035,7894.1
$6N85 on Top Layer (solid, remove dead copper, pour order 166): 7767.6,6518.7 7708.4,6518.7 7693.2,6533.9 7693.2,6686.6 7695.6,6689 7745.5,6689 7747.4,6687 7747.4,6573.9 7767.6,6553.7
5V_SYS on Top Layer (solid, remove dead copper, pour order 164): 7643.1,6618.7 7670.1,6618.7 7681.1,6607.7 7681.1,6557.2 7667.6,6543.7 7667.6,6518.7 7657.6,6508.7 7472.6,6508.7 7462.6,6518.7 7462.6,6573.7 7507.6,6618.7
$6N67 on Top Layer (solid, remove dead copper, pour order 150): 7517.6,8158.7 7557.6,8158.7 7562.6,8153.7 7562.6,8133.7 7597.6,8098.7 7597.6,7998.7 7587.6,7988.7 7527.6,7988.7 7522.6,7993.7 7522.6,8098.7 7512.6,8108.7 7512.6,8153.7
1V2_SYS on Top Layer (solid, remove dead copper, pour order 152): 7351.3,8180.7 7364.3,8193.7 7498.2,8193.7 7506.2,8185.7 7506.2,8132 7488.2,8114 7488.2,7994.3 7482.6,7988.7 7411.6,7988.7 7351.3,8048.9
$6N47 on Top Layer (solid, remove dead copper, pour order 162): 9040,7989.1 9040,7949.1 9035,7944.1 9015,7944.1 8980,7909.1 8880,7909.1 8870,7919.1 8870,7979.1 8875,7984.1 8980,7984.1 8990,7994.1 9035,7994.1
$1N39473 on VCC (solid, remove dead copper): 6807.3,6263.7 6787.6,6283.4 6787.6,6634 6807.3,6653.7 7012.9,6653.7 7032.6,6634 7032.6,6283.4 7012.9,6263.7

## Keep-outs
Top Layer:
  region: 8470.6,6742.9 8470.6,6713.4 8525.4,6713.4 8525.4,6742.9
  region: 8350.6,7101.4 8350.6,6672 8429.3,6672 8429.3,7101.4
  region: 8715.9,7122.2 8715.9,6672 8821,6672 8821,7122.2
  region: 8452.9,7097.2 8452.9,7067.7 8531.4,7067.7 8531.4,7097.2
  region: 8677.3,7114.9 8677.3,7085.4 8732.1,7085.4 8732.1,7114.9
  region: 8687.9,7682.2 8687.9,7636.2 8736.4,7636.2 8736.4,7682.2
  region: 8315.2,7984.9 8315.2,7938.8 8363.7,7938.8 8363.7,7984.9
  region: 8677.3,7439.7 8677.3,7374.8 8706.8,7374.8 8706.8,7439.7
  region: 8445.1,7990.8 8445.1,7944.7 8493.6,7944.7 8493.6,7990.8
  region: 8710.5,7588.5 8710.5,7542.4 8759,7542.4 8759,7588.5
VCC:
  region: 8624.4,7959.6 8624.4,7919.1 8661.9,7919.1 8661.9,7959.6
  region: 6723.6,6627.7 6723.6,6287.2 6782.1,6287.2 6782.1,6627.7
Bottom Layer:
  region: 8418.2,5791.8 8418.2,5706.8 8923.2,5706.8 8923.2,5791.8
  region: 8960.7,5791.8 8960.7,5706.8 9280.7,5706.8 9280.7,5791.8
Board Outline Layer:
  region: 8004.7,6184.2 8004.7,5928 8308.3,5928 8308.3,6184.2
  region: 8418.2,5971.8 8418.2,5711.8 8923.2,5711.8 8923.2,5971.8
  region: 8419.7,6126.8 8419.7,5977.9 9320.6,5977.9 9320.6,6126.8
  region: 8960.7,5971.8 8960.7,5711.8 9280.7,5711.8 9280.7,5971.8
  lines w3: 7037.5,6016.5 cw(c6958.8,6016.5) 6958.8,5937.8 6722.6,5937.8 6722.6,8300 6723,8307.7 6724.1,8315.3 6726,8322.8 6728.6,8330.1 6731.9,8337.1 6735.9,8343.7 6740.5,8349.9 6745.6,8355.6 6751.4,8360.8 6757.6,8365.4 6764.2,8369.4 6771.2,8372.7 6778.5,8375.3 6786,8377.2 6793.6,8378.3 6801.3,8378.7 9183.8,8378.7 cw(c9183.8,8300) 9262.5,8300 ; 7037.6,6016.5 7037.6,6183 cw(c7116.3,6183) 7116.3,6261.7 ; 7116.3,6261.8 7984.7,6261.8 7988.6,6261.4 7992.3,6260.3 7995.8,6258.4 7998.8,6255.9 8001.3,6252.9 8003.1,6249.4 8004.3,6245.7 8004.7,6241.8 8004.7,5928 8308.3,5928 8308.3,6184.2 8308.7,6192 8309.9,6199.8 8311.9,6207.4 8314.6,6214.8 8318.1,6221.9 8322.2,6228.5 8327.1,6234.8 8332.5,6240.5 8338.4,6245.6 8344.9,6250.1 8351.8,6253.9 8359,6257 8366.5,6259.4 8374.2,6260.9 8382,6261.7 8389.9,6261.7 8397.7,6260.9 8405.4,6259.4 8412.9,6257 8420.2,6253.9 8427,6250.1 8433.5,6245.6 8439.5,6240.5 8444.9,6234.8 8449.7,6228.5 8453.9,6221.9 8457.3,6214.8 8460.1,6207.4 8462,6199.8 8463.2,6192 8463.6,6184.2 8463.6,5761.8 8464,5757.9 8465.1,5754.1 8466.9,5750.7 8469.4,5747.6 8472.5,5745.2 8475.9,5743.3 8479.7,5742.2 8483.6,5741.8 8883.7,5741.8 8887.6,5742.2 8891.3,5743.3 8894.8,5745.2 8897.8,5747.6 8900.3,5750.7 8902.1,5754.1 8903.3,5757.9 8903.7,5761.8 8903.7,6035.6 8904.1,6040.9 8905.3,6046.1 8907.2,6051.1 8909.7,6055.7 8912.9,6060 8916.7,6063.7 8921,6066.9 8925.7,6069.4 8930.7,6071.3 8935.9,6072.4 8941.2,6072.8 8946.5,6072.4 8951.7,6071.3 8956.7,6069.4 8961.3,6066.9 8965.6,6063.7 8969.4,6060 8972.6,6055.7 8975.2,6051.1 8977.1,6046.1 8978.2,6040.9 8978.7,6035.6 8978.7,5761.8 8979.1,5757.9 8980.2,5754.1 8982,5750.7 8984.5,5747.6 8987.6,5745.2 8991,5743.3 8994.8,5742.2 8998.7,5741.8 9242.6,5741.8 9246.5,5742.2 9250.2,5743.3 9253.7,5745.2 9256.7,5747.6 9259.2,5750.7 9261.1,5754.1 9262.2,5757.9 9262.6,5761.8 9262.6,8300

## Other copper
Top Layer:
  region: 8642.6,8181.9 8640,8182.2 8637.6,8183.2 8635.6,8184.8 8634,8186.9 8633,8189.3 8632.6,8191.9 8632.6,8329.2 8633,8331.8 8634,8334.2 8635.6,8336.3 8637.6,8337.9 8640,8338.9 8642.6,8339.2 8705.4,8339.2 8706,8339.2 8706.7,8339.1 8712.8,8338.1 8718.7,8336.4 8724.4,8334 8729.8,8331 8734.9,8327.5 8739.5,8323.4 8743.6,8318.8 8747.2,8313.7 8750.2,8308.3 8752.5,8302.6 8754.2,8296.7 8755.3,8290.6 8755.6,8284.5 8755.3,8278.5 8754.3,8272.5 8752.7,8266.8 8750.4,8261.2 8747.6,8255.9 8744.2,8250.9 8740.3,8246.4 8735.9,8242.3 8731.1,8238.7 8725.9,8235.6 8753.7,8197.9 8754.8,8196.1 8755.4,8194.1 8755.6,8192 8755.3,8189.4 8754.3,8187 8752.7,8184.9 8750.6,8183.3 8748.2,8182.3 8745.6,8182 8743.3,8182.2 8741.1,8183 8739.2,8184.3 8737.6,8186 8701.9,8234.5 8700.8,8236.4 8700.2,8238.4 8699.9,8240.5 8700.3,8243.1 8701.4,8245.6 8703.1,8247.8 8705.3,8249.3 8707.9,8250.2 8712.4,8251.5 8716.8,8253.5 8720.9,8255.9 8724.6,8259 8727.8,8262.4 8730.5,8266.3 8732.7,8270.6 8734.3,8275.1 8735.3,8279.7 8735.6,8284.5 8735.2,8289.5 8734.1,8294.5 8732.3,8299.2 8729.9,8303.7 8726.8,8307.7 8723.2,8311.2 8719,8314.2 8714.5,8316.6 8709.8,8318.2 8704.8,8319.2 8652.6,8319.2 8652.6,8191.9 8652.3,8189.3 8651.3,8186.9 8649.7,8184.8 8647.6,8183.2 8645.2,8182.2
Bottom Layer:
  region: 8642.6,8340 8645.2,8339.7 8647.6,8338.7 8649.7,8337.1 8651.3,8335 8652.3,8332.6 8652.6,8330 8652.6,8202.7 8704.8,8202.7 8709.8,8203.7 8714.5,8205.3 8719,8207.7 8723.2,8210.7 8726.8,8214.2 8729.9,8218.3 8732.3,8222.7 8734.1,8227.4 8735.2,8232.4 8735.6,8237.4 8735.3,8242.2 8734.3,8246.9 8732.7,8251.3 8730.5,8255.6 8727.8,8259.5 8724.6,8263 8720.9,8266 8716.8,8268.5 8712.4,8270.4 8707.9,8271.7 8705.3,8272.6 8703.1,8274.2 8701.4,8276.3 8700.3,8278.8 8699.9,8281.5 8700.2,8283.6 8700.8,8285.6 8701.9,8287.4 8737.6,8335.9 8739.2,8337.6 8741.1,8338.9 8743.3,8339.7 8745.6,8340 8748.2,8339.6 8750.6,8338.6 8752.7,8337 8754.3,8335 8755.3,8332.5 8755.6,8330 8755.4,8327.9 8754.8,8325.9 8753.7,8324 8725.9,8286.3 8731.1,8283.2 8735.9,8279.6 8740.3,8275.5 8744.2,8271 8747.6,8266 8750.4,8260.7 8752.7,8255.2 8754.3,8249.4 8755.3,8243.4 8755.6,8237.4 8755.3,8231.3 8754.2,8225.2 8752.5,8219.3 8750.2,8213.6 8747.2,8208.2 8743.6,8203.1 8739.5,8198.5 8734.9,8194.4 8729.8,8190.9 8724.4,8187.9 8718.7,8185.5 8712.8,8183.8 8706.7,8182.8 8706,8182.7 8705.4,8182.7 8642.6,8182.7 8640,8183 8637.6,8184 8635.6,8185.6 8634,8187.7 8633,8190.1 8632.6,8192.7 8632.6,8330 8633,8332.6 8634,8335 8635.6,8337.1 8637.6,8338.7 8640,8339.7

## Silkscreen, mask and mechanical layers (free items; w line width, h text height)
Top Silkscreen Layer:
  lines w6.1: 8245.2,7036 8259.1,7022.1 8281.6,7022.1 8281.6,7050 8259.1,7050 8245.2,7036
  lines w10: 8939.5,6811.4 9147.7,6811.4 ; 8939.9,6611.4 9147.1,6611.4 ; 9147.5,7011.4 8937.6,7011.4 ; 9159.2,6301.4 8958.2,6301.4 8937.6,6322 8937.6,7500.7 8958.2,7521.4 9159.2,7521.4 ; 8937.6,7011.4 8987.6,7061.4 ; 8937.6,7011.4 8937.6,7111.4 ; 8937.6,7111.4 8987.6,7061.4 ; 8937.6,7111.4 9037.6,7111.4 ; 8987.6,7061.4 9037.6,7111.4 ; 8987.6,7061.4 9037.6,7011.4 9037.6,7111.4
  lines w11.8: 8987.6,6661.4 9087.6,6661.4 ; 8987.6,6761.4 9087.6,6761.4 ; 8987.6,6861.4 9087.6,6861.4 ; 8987.6,6961.4 9087.6,6961.4
  lines w20: 8902.7,8211.1 8897.2,8206.2 8891.2,8202 8884.9,8198.4 8878.2,8195.4 8871.2,8193.2 8864,8191.7 8856.7,8191 8849.4,8191.1 8842.2,8191.9 8835,8193.5 8828.1,8195.8 8821.4,8198.8 8815.1,8202.5 8809.2,8206.8 8803.8,8211.7 8798.9,8217.2 8794.6,8223.1 8791,8229.5 8788.1,8236.2 8785.8,8243.2 8784.3,8250.3 8783.6,8257.6 8783.6,8264.9 8784.4,8272.2 8786,8279.3 8788.3,8286.3 8791.3,8293 8795,8299.3 8799.3,8305.2 8804.2,8310.6 8809.7,8315.5 8815.6,8319.8 8821.9,8323.4 8828.6,8326.4 8835.6,8328.6 8842.8,8330.1 8850,8330.9 8857.4,8330.9 8864.6,8330.1 8871.8,8328.5 8878.7,8326.3 8885.4,8323.3 8891.8,8319.6 8897.7,8315.3 8903.1,8310.4 ; 9108.6,8233.8 ccw(c9150.6,8233.8) 9141.65,8192.76 ; 9112.6,8294.81 ccw(c9145.2,8302.1) 9136.61,8269.82 ; 9112.7,8294.83 cw(c9142.7,8299.1) 9119.69,8318.82 ; 9119.63,8318.87 cw(c9149.7,8293.1) 9141.67,8331.88 ; 9136.58,8269.85 ccw(c9406.9,9285.8) 9186.53,8257.86 ; 9141.65,8192.86 ccw(c9160.8,8280.7) 9190.51,8195.85 ; 9141.7,8331.78 cw(c9159.5,8245.8) 9171.57,8332.77 ; 9171.63,8332.75 cw(c9165.1,8285.7) 9190.62,8325.76 ; 9186.67,8257.78 cw(c9179.9,8226.2) 9209.63,8238.82 cw(c9180,8226.2) 9190.64,8195.81 ; 9190.67,8325.84 cw(c9170.9,8294.8) 9207.7,8294.8 ; 9136.6,8269.8 9136.6,8269.8 ; 9141.6,8192.8 9141.6,8192.8 ; 9186.6,8257.8 9186.6,8257.8
  text "MIPI" at 8164.1,7663 h45 r270
  text "Prototype / V2.4A6" at 7862.4,7156.3 h78.7
  text "IO2 SDA / IO3 SCL / GND GND" at 8871.8,6129.6 h59.1
Bottom Silkscreen Layer:
  drawing of 105 lines, arcs and shapes, not listed
  text "Prototype / V2.4A6" at 7023.8,8366.9 h78.7 r180
  text "EXOANCHOR" at 7403.1,7894 h196.9 r180
  text "USB" at 8825,7202.3 h78.7 r90
  text "RST" at 8729,6852.3 h78.7 r90
  text "RST" at 8828.7,6852.3 h78.7 r90
  text "PWR" at 8728.7,6652.3 h78.7 r90
  text "PWR" at 8828.7,6652.3 h78.7 r90
  text "GPIO2 SDA" at 8435.2,6522 h78.7 r180
  text "GPIO3 SCL" at 8435.2,6422 h78.7 r180
  text "GND" at 8748.2,6322 h78.7 r180
Top Solder Mask Layer:
  region: 8004.6,6174.2 8004.6,5928 8308.2,5928 8308.2,6174.2
  region: 8418.2,5966.8 8418.2,5706.8 8938.2,5706.8 8938.2,5966.8
  region: 8948.2,5966.8 8948.2,5706.8 9288.2,5706.8 9288.2,5966.8
Bottom Solder Mask Layer:
  region: 8004.7,6174.2 8004.7,5928 8308.3,5928 8308.3,6174.2
  region: 8418.2,5966.8 8418.2,5706.8 8938.2,5706.8 8938.2,5966.8
  region: 8948.2,5966.8 8948.2,5706.8 9288.2,5706.8 9288.2,5966.8

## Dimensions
5836.8,8221.2 to 5836.8,6095.2 on Document Layer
